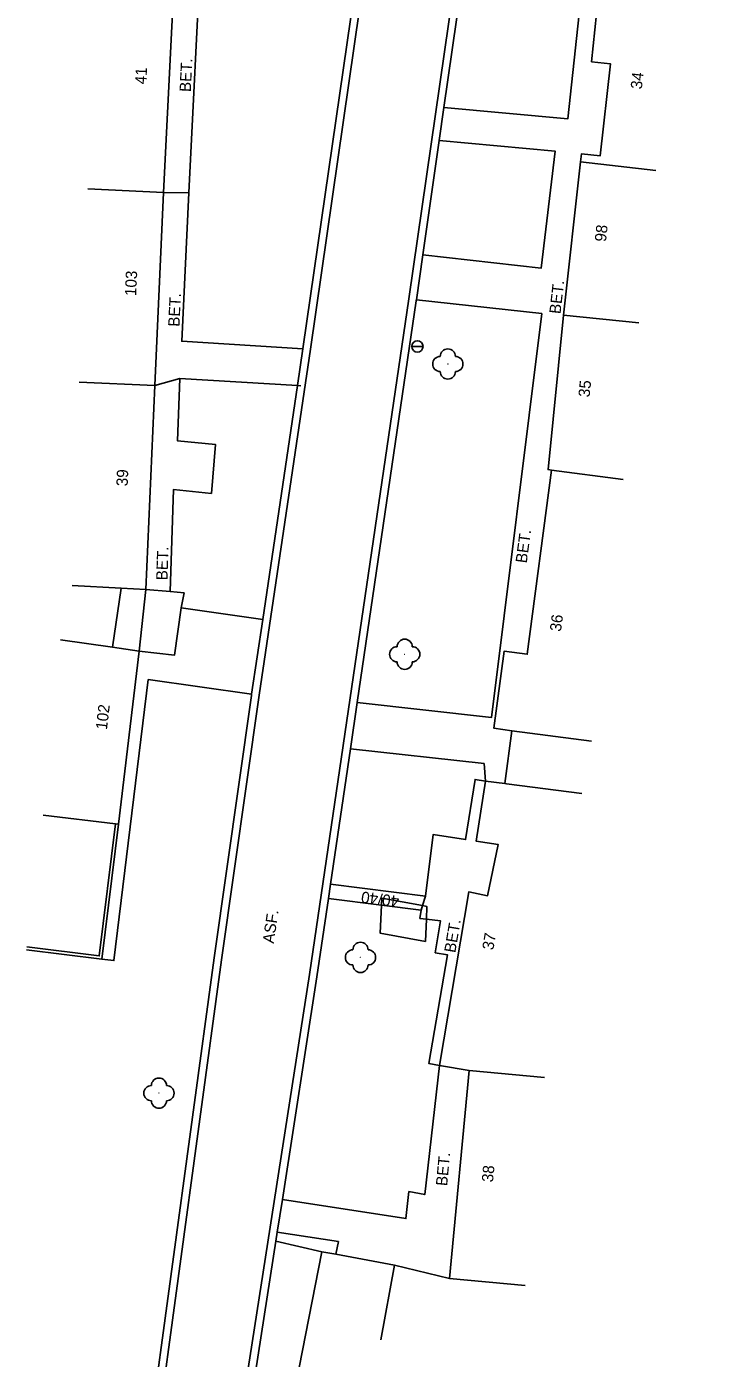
# Model space of a CAD drawing. Extents: x -544674 to -541478, y -1199076 to -1195527.
# Drawn here: x -543791.7 to -543747.1, y -1197346.5 to -1197258.5 of the extents above; entities that cross this region are included whole.
import ezdxf

# ---------------------------------------------------------------- set-up
doc = ezdxf.new("R2010")
doc.units = 0
for name, color, linetype in [('BUDOVY_MĚŘ', 7, 'Continuous'), ('POMOC_POPIS', 7, 'Continuous'), ('ROZHRANÍ_PLOCH', 7, 'Continuous'), ('ZELEŇ', 7, 'Continuous'), ('ZN_DOPLŇKOVÉ', 7, 'Continuous'), ('Č_POPIS_ORIENT', 7, 'Continuous')]:
    doc.layers.add(name, color=color, linetype=linetype)

msp = doc.modelspace()

# ---------------------------------------------------------------- linework, layer by layer
at = {"layer": 'BUDOVY_MĚŘ'}
for points in [[(-543782.68, -1197269.51), (-543781.87, -1197253.25)], [(-543755.13, -1197267.49), (-543755.07, -1197266.95), (-543753.84, -1197267.09), (-543753.16, -1197261), (-543754.41, -1197260.87), (-543753.86, -1197255.57)], [(-543756.26, -1197277.62), (-543755.13, -1197267.49)], [(-543750.16, -1197268.05), (-543755.13, -1197267.49)], [(-543787.67, -1197269.26), (-543782.68, -1197269.51)], [(-543783.26, -1197282.26), (-543782.68, -1197269.51)], [(-543757.05, -1197287.85), (-543757.28, -1197287.82), (-543756.26, -1197277.62)], [(-543751.29, -1197278.12), (-543756.26, -1197277.62)], [(-543788.26, -1197282.03), (-543783.26, -1197282.26)], [(-543783.84, -1197295.74), (-543783.26, -1197282.26)], [(-543757.05, -1197287.85), (-543758.66, -1197300.02), (-543760.19, -1197299.82), (-543760.86, -1197304.91), (-543759.67, -1197305.07)], [(-543752.32, -1197288.47), (-543757.05, -1197287.85)], [(-543788.72, -1197295.47), (-543785.47, -1197295.65)], [(-543785.47, -1197295.65), (-543783.84, -1197295.74)], [(-543786.05, -1197299.56), (-543789.49, -1197299.07)], [(-543784.29, -1197299.81), (-543786.05, -1197299.56)], [(-543785.65, -1197311.25), (-543784.29, -1197299.81)], [(-543759.67, -1197305.07), (-543754.42, -1197305.76)], [(-543761.41, -1197308.4), (-543762.02, -1197312.38), (-543760.57, -1197312.6), (-543761.28, -1197315.98), (-543762.52, -1197315.72), (-543764.46, -1197327.19)], [(-543760.14, -1197308.56), (-543761.41, -1197308.4)], [(-543755.06, -1197309.23), (-543760.02, -1197308.58), (-543760.14, -1197308.56)], [(-543790.62, -1197310.66), (-543785.85, -1197311.23)], [(-543785.85, -1197311.23), (-543785.65, -1197311.25)], [(-543764.46, -1197327.19), (-543762.49, -1197327.52)], [(-543762.49, -1197327.52), (-543763.78, -1197341.27)], [(-543757.51, -1197327.99), (-543762.49, -1197327.52)], [(-543772.22, -1197339.5), (-543775.86, -1197358.05)], [(-543771.29, -1197339.67), (-543772.22, -1197339.5)], [(-543767.42, -1197340.39), (-543771.29, -1197339.67)], [(-543768.33, -1197345.31), (-543767.42, -1197340.39)], [(-543763.78, -1197341.27), (-543758.8, -1197341.74)]]:
    msp.add_lwpolyline(points, dxfattribs=at)
at = {"layer": 'ROZHRANÍ_PLOCH'}
for points in [[(-543747.09, -1197143.18), (-543749.99, -1197163.05), (-543753.06, -1197183.49), (-543754.87, -1197195.24), (-543758.02, -1197218.14), (-543761.58, -1197242.21), (-543763.27, -1197254.24), (-543766.48, -1197276.53), (-543773.03, -1197321.19), (-543778.69, -1197357.55)], [(-543784.42, -1197358.89), (-543783.15, -1197351.8), (-543778.85, -1197320.21), (-543776.36, -1197302.72), (-543772.98, -1197279.86), (-543769.35, -1197254.78), (-543766.98, -1197238.27), (-543764.15, -1197218.92)], [(-543764.16, -1197263.89), (-543755.97, -1197264.63), (-543754.99, -1197255.43), (-543756.74, -1197255.03), (-543756.18, -1197252.08), (-543754.73, -1197252.13), (-543753.78, -1197243.24), (-543761.09, -1197242.27)], [(-543761.09, -1197242.27), (-543762.75, -1197254.11), (-543764.16, -1197263.89)], [(-543781.01, -1197269.53), (-543780.19, -1197253.17)], [(-543769.84, -1197254.71), (-543773.46, -1197279.69), (-543773.48, -1197279.83)], [(-543764.16, -1197263.89), (-543764.47, -1197266.08)], [(-543764.47, -1197266.08), (-543765.55, -1197273.63)], [(-543764.47, -1197266.08), (-543756.82, -1197266.77), (-543757.73, -1197274.5), (-543765.55, -1197273.63)], [(-543781.01, -1197269.53), (-543782.68, -1197269.51)], [(-543773.48, -1197279.83), (-543781.48, -1197279.34), (-543781.01, -1197269.53)], [(-543765.55, -1197273.63), (-543765.98, -1197276.59)], [(-543765.98, -1197276.59), (-543757.7, -1197277.51), (-543761.01, -1197304.19), (-543769.89, -1197303.21)], [(-543765.98, -1197276.59), (-543765.99, -1197276.66), (-543769.89, -1197303.21)], [(-543773.48, -1197279.83), (-543773.84, -1197282.27)], [(-543781.61, -1197281.79), (-543783.26, -1197282.26)], [(-543782.24, -1197295.87), (-543782.03, -1197289.14), (-543779.52, -1197289.39), (-543779.24, -1197286.17), (-543781.75, -1197285.92), (-543781.61, -1197281.79)], [(-543781.61, -1197281.79), (-543773.84, -1197282.27)], [(-543773.84, -1197282.27), (-543776.13, -1197297.72)], [(-543773.84, -1197282.27), (-543773.61, -1197282.28)], [(-543786.05, -1197299.56), (-543785.47, -1197295.65)], [(-543784.29, -1197299.81), (-543783.84, -1197295.74)], [(-543783.84, -1197295.74), (-543782.24, -1197295.87)], [(-543782.24, -1197295.87), (-543781.32, -1197295.97), (-543781.52, -1197296.96)], [(-543781.52, -1197296.96), (-543781.96, -1197300.09), (-543784.29, -1197299.81)], [(-543776.13, -1197297.72), (-543781.52, -1197296.96)], [(-543776.13, -1197297.72), (-543776.86, -1197302.65)], [(-543776.86, -1197302.65), (-543783.69, -1197301.69), (-543785.96, -1197320.26), (-543786.76, -1197320.17)], [(-543776.86, -1197302.65), (-543776.87, -1197302.75), (-543779.34, -1197320.08), (-543783.63, -1197351.67), (-543784.42, -1197358.89)], [(-543769.89, -1197303.21), (-543770.34, -1197306.27)], [(-543770.34, -1197306.27), (-543771.65, -1197315.22)], [(-543770.34, -1197306.27), (-543761.51, -1197307.24), (-543761.41, -1197308.4)], [(-543761.41, -1197308.4), (-543762.1, -1197308.29), (-543762.73, -1197312.26), (-543764.86, -1197311.92), (-543765.37, -1197316.01)], [(-543771.65, -1197315.22), (-543771.79, -1197316.15)], [(-543771.65, -1197315.22), (-543765.37, -1197316.01)], [(-543771.79, -1197316.15), (-543772.55, -1197321.33), (-543774.83, -1197336.04)], [(-543771.79, -1197316.15), (-543768.29, -1197316.59)], [(-543768.29, -1197316.59), (-543768.36, -1197318.45), (-543765.38, -1197318.99), (-543765.32, -1197317.52)], [(-543765.57, -1197316.63), (-543768.27, -1197316.14), (-543768.29, -1197316.59)], [(-543768.29, -1197316.59), (-543765.67, -1197316.92)], [(-543765.67, -1197316.92), (-543765.57, -1197316.63)], [(-543765.57, -1197316.63), (-543765.37, -1197316.01)], [(-543765.32, -1197317.52), (-543765.29, -1197316.68), (-543765.57, -1197316.63)], [(-543765.67, -1197316.92), (-543765.74, -1197317.47), (-543765.32, -1197317.52)], [(-543765.32, -1197317.52), (-543764.38, -1197317.64), (-543764.73, -1197319.74), (-543763.93, -1197319.88), (-543765.15, -1197327.07), (-543764.46, -1197327.19)], [(-543764.46, -1197327.19), (-543765.43, -1197335.72), (-543766.47, -1197335.53), (-543766.67, -1197337.31), (-543774.83, -1197336.04)], [(-543774.83, -1197336.04), (-543775.17, -1197338.2)], [(-543775.17, -1197338.2), (-543775.26, -1197338.79)], [(-543775.17, -1197338.2), (-543771.13, -1197338.83), (-543771.29, -1197339.67)], [(-543775.26, -1197338.79), (-543778.2, -1197357.68)], [(-543772.22, -1197339.5), (-543775.26, -1197338.79)]]:
    msp.add_lwpolyline(points, dxfattribs=at)
at = {"layer": 'ZELEŇ'}
for centre in [(-543763.9, -1197280.84), (-543766.75, -1197300.02), (-543769.67, -1197320.05), (-543782.98, -1197329.02)]:
    msp.add_circle(centre, 0.0005, dxfattribs=at)
for centre, start, end in [((-543764.4, -1197280.84), 89.99999, 269.99999), ((-543763.9, -1197280.34), 0, 179.99999), ((-543763.4, -1197280.84), 270, 89.99999), ((-543763.9, -1197281.34), 179.99999, 359.99999), ((-543766.75, -1197299.52), 0, 179.99999), ((-543767.25, -1197300.02), 89.99999, 269.99999), ((-543766.25, -1197300.02), 270, 89.99999), ((-543766.75, -1197300.52), 179.99999, 359.99999), ((-543769.67, -1197319.55), 0, 179.99999), ((-543770.17, -1197320.05), 89.99999, 269.99999), ((-543769.17, -1197320.05), 270, 89.99999), ((-543769.67, -1197320.55), 179.99999, 359.99999), ((-543782.98, -1197328.52), 0, 179.99999), ((-543783.48, -1197329.02), 89.99999, 269.99999), ((-543782.48, -1197329.02), 270, 89.99999), ((-543782.98, -1197329.52), 179.99999, 359.99999)]:
    msp.add_arc(centre, 0.5, start, end, dxfattribs=at)
at = {"layer": 'ZN_DOPLŇKOVÉ'}
msp.add_line((-543766.285, -1197279.68), (-543765.535, -1197279.68), dxfattribs=at)
for points in [[(-543759.67, -1197305.07), (-543760.14, -1197308.56)], [(-543785.85, -1197311.23), (-543786.93, -1197319.95), (-543791.7, -1197319.35)], [(-543785.65, -1197311.25), (-543786.76, -1197320.17)], [(-543786.76, -1197320.17), (-543791.72, -1197319.55)], [(-543767.42, -1197340.39), (-543763.78, -1197341.27)]]:
    msp.add_lwpolyline(points, dxfattribs=at)
msp.add_circle((-543765.91, -1197279.68), 0.375, dxfattribs=at)

# ---------------------------------------------------------------- texts
at = {"layer": 'POMOC_POPIS'}
for s, rotation, p in [('BET.', 87.14997, (-543780.88, -1197262.88)), ('BET.', 87.25998, (-543781.63, -1197278.39)), ('BET.', 83.63001, (-543756.46, -1197277.56)), ('BET.', 82.48002, (-543758.69, -1197294.03)), ('BET.', 88.21, (-543782.42, -1197295.14)), ('40/40', 172.84, (-543767.08, -1197316)), ('ASF.', 81.66001, (-543775.4, -1197319.16)), ('BET.', 80.40002, (-543763.41, -1197319.78)), ('BET.', 84.62999, (-543763.95, -1197335.18))]:
    msp.add_text(s, height=0.75, rotation=rotation, dxfattribs=at).set_placement(p)
at = {"layer": 'Č_POPIS_ORIENT'}
for s, rotation, p in [('41', 87.14997, (-543783.82, -1197262.37)), ('34', 83.65, (-543751.09, -1197262.71)), ('98', 83.63001, (-543753.46, -1197272.79)), ('103', 87.40001, (-543784.49, -1197276.36)), ('35', 84.29, (-543754.54, -1197283.06)), ('39', 87.53999, (-543785.05, -1197288.93)), ('36', 82.48002, (-543756.43, -1197298.55)), ('102', 83.22, (-543786.42, -1197305.04)), ('37', 80.40002, (-543760.9, -1197319.6)), ('38', 84.62999, (-543760.92, -1197334.93))]:
    msp.add_text(s, height=0.75, rotation=rotation, dxfattribs=at).set_placement(p)

doc.saveas('drawing.dxf')
